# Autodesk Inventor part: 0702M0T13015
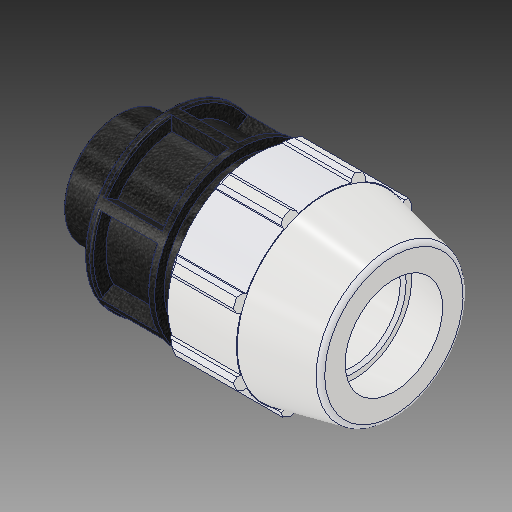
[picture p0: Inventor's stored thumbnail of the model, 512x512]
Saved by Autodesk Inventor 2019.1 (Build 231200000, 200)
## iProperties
Created: 2017-02
Part Number: 0702M0T13015
Material: PVC-Piping
Description: PLASSON MALE ADAPTOR 1 1/4'' - 1 1/2''M
Document SubType Name: Modeling
Designer: KIM
Mass: 92.6774 g
Surface Area: 199.44 cm^2
Volume: 66.1981 cm^3
Density: 1.4 g/cm^3
Appearance: PTFE
Author: KIM
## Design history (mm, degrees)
derived "0702M0T.ipt"
feature "Solid1::0702M0T.ipt"
tag "TaggingFeature1"
body "Solid1"
other parameters: "d2" = 42.1, "d4" = 17.018, "d5" = 29.7815, "d7" = 82.042, "d8" = 61.5315, "d9" = 17.018, "d11" = 3.4036, "d12" = 65.6336, "d13" = 120 deg, "d14" = 63.15, "d15" = 12 deg, "d16" = 73.8378, "d18" = 2.105, "d19" = 35 deg, "d20" = 17.5 deg, "d21" = 76.29906, "d23" = 0, "d25" = 360 deg, "d27" = 1.64084, "d34" = 4.1021, "d36" = 0, "d42" = 29.7815, "d43" = 2.46126, "d46" = 1.263, "d51" = 119.126, "d52" = 22.098, "d53" = 0.842, "d55" = 360 deg, "d57" = 47.803, "d58" = 33.4621, "d59" = 23.8252, "d61" = 27.178, "d_" = 42.1, "E_" = 82.042, "H_" = 119.126, "l_" = 90.932, "l_2" = 22.098, "G_" = 47.803
